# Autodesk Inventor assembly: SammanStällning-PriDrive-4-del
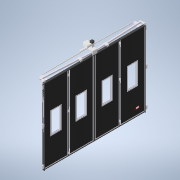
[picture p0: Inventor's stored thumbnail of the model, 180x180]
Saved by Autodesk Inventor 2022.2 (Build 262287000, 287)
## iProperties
Created: 2022-02
Part Number: SammanStällning-PriDrive-4-del
Document SubType Name: Assembly
Designer: cl
Author: cl
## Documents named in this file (23)
- G:\AutoCad\Carl Lund\3D-modeller systemlösningar\3D-modell-systemlösning-2022\SammanStällning-PriDrive-4-del.iam
- G:\AutoCad\Carl Lund\3D-modeller systemlösningar\3D-modell-systemlösning-2022\Parts\BladKomplett2022.iam
- G:\AutoCad\Carl Lund\3D-modeller systemlösningar\3D-modell-systemlösning-2022\Parts\MellanGångjärnH.ipt
- G:\AutoCad\Carl Lund\3D-modeller systemlösningar\3D-modell-systemlösning-2022\Parts\MellanGångjärnV.ipt
- G:\AutoCad\Carl Lund\3D-modeller systemlösningar\3D-modell-systemlösning-2022\Parts\Karmstyrning.ipt
- G:\AutoCad\Carl Lund\3D-modeller systemlösningar\3D-modell-systemlösning-2022\Parts\SidotätningUppe.ipt
- G:\AutoCad\Carl Lund\3D-modeller systemlösningar\3D-modell-systemlösning-2022\Parts\SidoTätning.ipt
- G:\AutoCad\Carl Lund\3D-modeller systemlösningar\3D-modell-systemlösning-2022\Parts\SläpList.ipt
- G:\AutoCad\Carl Lund\3D-modeller systemlösningar\3D-modell-systemlösning-2022\Parts\GummilistMellan.ipt
- G:\AutoCad\Carl Lund\3D-modeller systemlösningar\3D-modell-systemlösning-2022\Styrande.iam
- G:\AutoCad\Carl Lund\3D-modeller systemlösningar\3D-modell-systemlösning-2022\Parts\PriDrive\Karmgångjärn-PriDrive.ipt
- G:\AutoCad\Carl Lund\3D-modeller systemlösningar\3D-modell-systemlösning-2022\Parts\PriDrive\VinkeljärnStyrskena2.ipt
- G:\AutoCad\Carl Lund\3D-modeller systemlösningar\3D-modell-systemlösning-2022\Parts\PriDrive\VinkeljärnStyrskena.ipt
- G:\AutoCad\Carl Lund\3D-modeller systemlösningar\3D-modell-systemlösning-2022\Parts\StyrrulleH.ipt
- G:\AutoCad\Carl Lund\3D-modeller systemlösningar\3D-modell-systemlösning-2022\Parts\StyrrulleV.ipt
- G:\AutoCad\Carl Lund\3D-modeller systemlösningar\3D-modell-systemlösning-2022\Parts\MotorPlatta.ipt
- G:\AutoCad\Carl Lund\3D-modeller systemlösningar\3D-modell-systemlösning-2022\Parts\Länkarm-4Del.ipt
- G:\AutoCad\Carl Lund\3D-modeller systemlösningar\3D-modell-systemlösning-2022\Parts\Länkarm2-4Del.ipt
- G:\AutoCad\Carl Lund\3D-modeller systemlösningar\3D-modell-systemlösning-2022\Parts\MotorKåpa.ipt
- G:\AutoCad\Carl Lund\3D-modeller systemlösningar\3D-modell-systemlösning-2022\Parts\Motor.ipt
- G:\AutoCad\Carl Lund\3D-modeller systemlösningar\3D-modell-systemlösning-2022\Parts\Växellåda.ipt
- G:\AutoCad\Carl Lund\3D-modeller systemlösningar\3D-modell-systemlösning-2022\Parts\Styrskena-PD.ipt
- G:\AutoCad\Carl Lund\3D-modeller systemlösningar\3D-modell-systemlösning-2022\Parts\Logga.ipt
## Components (47 placed, 21 different names)
1. Logga:1 — Mate:196, Mate:197, Mate:198
2. BladKomplett2022:1 [sub-assembly] — Mate:1, Mate:2, Flush:1, Flush:2, Flush:3, Flush:8, Flush:28, Flush:29, Mate:28, Flush:30, Mate:42, Mate:39, Mate:43, Flush:99, Flush:100, Flush:101, Flush:102, Flush:103, Flush:104, Flush:112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
3. BladKomplett2022:2 [sub-assembly] — Flush:2, Flush:3, Flush:8, Flush:106, Mate:52, Flush:107, Flush:118, Flush:121, Mate:65, Flush:148, Flush:149, Mate:185, Flush:182, Flush:183, Flush:188, Mate:189
4. BladKomplett2022:3 [sub-assembly] — Flush:30, Flush:101, Flush:102, Mate:53, Flush:114, Flush:115, Flush:180
5. BladKomplett2022:4 [sub-assembly] — Flush:32, Flush:100, Flush:103, Mate:54, Flush:122, Flush:123, Flush:128, Mate:64, Flush:146, Flush:147, Flush:178
6. BladKomplett2022:5 [sub-assembly] — Flush:31, Flush:99, Flush:104, Flush:129, Mate:55, Flush:130, Mate:63, Flush:144, Flush:145, Mate:186, Flush:184, Flush:185, Flush:186, Flush:189
7. BladKomplett2022:6 [sub-assembly] — Mate:28, Flush:28, Flush:29, Flush:31, Flush:32, Mate:38, Flush:131, Flush:134, Flush:137, Mate:56, Flush:138, Flush:139, Mate:58, Mate:59, Mate:62, Flush:142, Flush:143, Flush:152, Mate:69, Mate:70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
8. Karmstyrning:2 — Mate:38, Mate:56, Flush:138, Flush:141
9. Karmstyrning:3 — Mate:39, Mate:43, Flush:140
10. Karmstyrning:4 — Mate:42, Mate:60, Mate:61, Flush:141
11. Karmstyrning:1 — Flush:139, Mate:58, Mate:59, Flush:140
12. MellanGångjärnV:3 — Flush:110, Flush:111, Flush:113
13. MellanGångjärnV:2 — Flush:108, Flush:109, Flush:110, Flush:111, Flush:112
14. MellanGångjärnV:1 — Flush:106, Mate:52, Flush:107, Flush:108, Flush:109
15. MellanGångjärnH:2 — Flush:116, Flush:117, Flush:118, Flush:119, Flush:120
16. MellanGångjärnH:3 — Flush:119, Flush:120, Flush:121
17. MellanGångjärnH:1 — Mate:53, Flush:114, Flush:115, Flush:116, Flush:117
18. MellanGångjärnV:6 — Flush:124, Flush:125, Flush:126, Flush:127, Flush:128
19. MellanGångjärnV:5 — Flush:126, Flush:127, Flush:129
20. MellanGångjärnV:4 — Mate:54, Flush:122, Flush:123, Flush:124, Flush:125
21. MellanGångjärnH:5 — Flush:132, Flush:133, Flush:134
22. MellanGångjärnH:6 — Flush:135, Flush:136, Flush:137
23. MellanGångjärnH:4 — Mate:55, Flush:130, Flush:131, Flush:132, Flush:133, Flush:135, Flush:136
24. GummilistMellan:2 — Mate:63, Flush:144, Flush:145
25. GummilistMellan:3 — Mate:64, Flush:146, Flush:147
26. GummilistMellan:4 — Mate:65, Flush:148, Flush:149
27. GummilistMellan:5 — Mate:66, Flush:150, Flush:151
28. SidotätningUppe:1 — Mate:67, Mate:68, Flush:152, Mate:71, Mate:74
29. SidoTätning:1 — Mate:69, Mate:70, Mate:71, Mate:76
30. SidoTätning:2 — Mate:72, Mate:73, Mate:74
31. SläpList:1 — Mate:75, Flush:153, Mate:76
32. GummilistMellan:1 — Mate:62, Flush:142, Flush:143
33. Karmgångjärn-PriDrive:1 — Mate:177, Flush:176, Mate:178, Flush:177, Flush:179, Mate:188, Tangent:3, Tangent:4
34. VinkeljärnStyrskena2:1 — Flush:179, Flush:180, Mate:181, Mate:183, Flush:187
35. VinkeljärnStyrskena2:2 — Flush:177, Flush:178, Mate:180, Flush:181, Mate:184
36. VinkeljärnStyrskena:1 — Mate:182, Flush:181, Flush:186
37. VinkeljärnStyrskena:2 — Mate:187, Flush:187, Flush:188
38. StyrrulleH:1 — Mate:185, Flush:182, Flush:183, Tangent:2
39. StyrrulleV:1 — Mate:186, Flush:184, Flush:185, Tangent:1
40. Styrskena-PD:2 — Flush:174, Mate:181, Mate:183, Tangent:2, Mate:187
41. Styrskena-PD:1 — Flush:174, Mate:179, Mate:180, Mate:182, Mate:184, Tangent:1
42. Länkarm-4Del:1 — Flush:190, Mate:190, Tangent:3, Flush:191
43. Länkarm2-4Del:1 — Mate:191, Flush:191, Tangent:4
44. MotorKåpa:1 — Mate:195, Flush:195, Flush:196
45. Motor:1 — Mate:193, Flush:194, Mate:194, Mate:195, Flush:195, Flush:196
46. Växellåda:1 — Mate:192, Flush:192, Flush:193, Flush:194, Mate:194
47. MotorPlatta:1 — Mate:188, Flush:189, Mate:189, Flush:190, Mate:190, Mate:191, Mate:192, Flush:192, Flush:193, Mate:193
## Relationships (142: Flush 85, Mate 53, Tangent 4)
- Mate:1: BladKomplett2022:1
- Mate:2: BladKomplett2022:1
- Flush:1: BladKomplett2022:1
- Flush:2: BladKomplett2022:1 ↔ BladKomplett2022:2
- Flush:3: BladKomplett2022:1 ↔ BladKomplett2022:2
- Flush:8: BladKomplett2022:1 ↔ BladKomplett2022:2
- Mate:28: BladKomplett2022:1 ↔ BladKomplett2022:6
- Flush:28: BladKomplett2022:1 ↔ BladKomplett2022:6
- Flush:29: BladKomplett2022:1 ↔ BladKomplett2022:6
- Flush:30: BladKomplett2022:1 ↔ BladKomplett2022:3
- Flush:31: BladKomplett2022:5 ↔ BladKomplett2022:6
- Flush:32: BladKomplett2022:4 ↔ BladKomplett2022:6
- Mate:38: BladKomplett2022:6 ↔ Karmstyrning:2
- Mate:39: BladKomplett2022:1 ↔ Karmstyrning:3
- Mate:42: BladKomplett2022:1 ↔ Karmstyrning:4
- Mate:43: BladKomplett2022:1 ↔ Karmstyrning:3
- Flush:99: BladKomplett2022:1 ↔ BladKomplett2022:5
- Flush:100: BladKomplett2022:1 ↔ BladKomplett2022:4
- Flush:101: BladKomplett2022:1 ↔ BladKomplett2022:3
- Flush:102: BladKomplett2022:1 ↔ BladKomplett2022:3
- Flush:103: BladKomplett2022:1 ↔ BladKomplett2022:4
- Flush:104: BladKomplett2022:1 ↔ BladKomplett2022:5
- Flush:106: BladKomplett2022:2 ↔ MellanGångjärnV:1
- Mate:52: BladKomplett2022:2 ↔ MellanGångjärnV:1
- Flush:107: BladKomplett2022:2 ↔ MellanGångjärnV:1
- Flush:108: MellanGångjärnV:2 ↔ MellanGångjärnV:1
- Flush:109: MellanGångjärnV:2 ↔ MellanGångjärnV:1
- Flush:110: MellanGångjärnV:3 ↔ MellanGångjärnV:2
- Flush:111: MellanGångjärnV:3 ↔ MellanGångjärnV:2
- Flush:112: BladKomplett2022:1 ↔ MellanGångjärnV:2
- Flush:113: BladKomplett2022:1 ↔ MellanGångjärnV:3
- Mate:53: BladKomplett2022:3 ↔ MellanGångjärnH:1
- Flush:114: BladKomplett2022:3 ↔ MellanGångjärnH:1
- Flush:115: BladKomplett2022:3 ↔ MellanGångjärnH:1
- Flush:116: MellanGångjärnH:2 ↔ MellanGångjärnH:1
- Flush:117: MellanGångjärnH:2 ↔ MellanGångjärnH:1
- Flush:118: BladKomplett2022:2 ↔ MellanGångjärnH:2
- Flush:119: MellanGångjärnH:2 ↔ MellanGångjärnH:3
- Flush:120: MellanGångjärnH:2 ↔ MellanGångjärnH:3
- Flush:121: BladKomplett2022:2 ↔ MellanGångjärnH:3
- Mate:54: BladKomplett2022:4 ↔ MellanGångjärnV:4
- Flush:122: BladKomplett2022:4 ↔ MellanGångjärnV:4
- Flush:123: BladKomplett2022:4 ↔ MellanGångjärnV:4
- Flush:124: MellanGångjärnV:6 ↔ MellanGångjärnV:4
- Flush:125: MellanGångjärnV:6 ↔ MellanGångjärnV:4
- Flush:126: MellanGångjärnV:6 ↔ MellanGångjärnV:5
- Flush:127: MellanGångjärnV:6 ↔ MellanGångjärnV:5
- Flush:128: BladKomplett2022:4 ↔ MellanGångjärnV:6
- Flush:129: BladKomplett2022:5 ↔ MellanGångjärnV:5
- Mate:55: BladKomplett2022:5 ↔ MellanGångjärnH:4
- Flush:130: BladKomplett2022:5 ↔ MellanGångjärnH:4
- Flush:131: BladKomplett2022:6 ↔ MellanGångjärnH:4
- Flush:132: MellanGångjärnH:5 ↔ MellanGångjärnH:4
- Flush:133: MellanGångjärnH:5 ↔ MellanGångjärnH:4
- Flush:134: BladKomplett2022:6 ↔ MellanGångjärnH:5
- Flush:135: MellanGångjärnH:6 ↔ MellanGångjärnH:4
- Flush:136: MellanGångjärnH:6 ↔ MellanGångjärnH:4
- Flush:137: BladKomplett2022:6 ↔ MellanGångjärnH:6
- Mate:56: BladKomplett2022:6 ↔ Karmstyrning:2
- Flush:138: BladKomplett2022:6 ↔ Karmstyrning:2
- Flush:139: BladKomplett2022:6 ↔ Karmstyrning:1
- Mate:58: BladKomplett2022:6 ↔ Karmstyrning:1
- Mate:59: BladKomplett2022:6 ↔ Karmstyrning:1
- Flush:140: Karmstyrning:3 ↔ Karmstyrning:1
- Mate:60: BladKomplett2022:1 ↔ Karmstyrning:4
- Mate:61: BladKomplett2022:1 ↔ Karmstyrning:4
- Flush:141: Karmstyrning:2 ↔ Karmstyrning:4
- Mate:62: BladKomplett2022:6 ↔ GummilistMellan:1
- Flush:142: BladKomplett2022:6 ↔ GummilistMellan:1
- Flush:143: BladKomplett2022:6 ↔ GummilistMellan:1
- Mate:63: BladKomplett2022:5 ↔ GummilistMellan:2
- Flush:144: BladKomplett2022:5 ↔ GummilistMellan:2
- Flush:145: BladKomplett2022:5 ↔ GummilistMellan:2
- Mate:64: BladKomplett2022:4 ↔ GummilistMellan:3
- Flush:146: BladKomplett2022:4 ↔ GummilistMellan:3
- Flush:147: BladKomplett2022:4 ↔ GummilistMellan:3
- Mate:65: BladKomplett2022:2 ↔ GummilistMellan:4
- Flush:148: BladKomplett2022:2 ↔ GummilistMellan:4
- Flush:149: BladKomplett2022:2 ↔ GummilistMellan:4
- Mate:66: BladKomplett2022:1 ↔ GummilistMellan:5
- Flush:150: BladKomplett2022:1 ↔ GummilistMellan:5
- Flush:151: BladKomplett2022:1 ↔ GummilistMellan:5
- Mate:67: BladKomplett2022:1 ↔ SidotätningUppe:1
- Mate:68: BladKomplett2022:1 ↔ SidotätningUppe:1
- Flush:152: BladKomplett2022:6 ↔ SidotätningUppe:1
- Mate:69: BladKomplett2022:6 ↔ SidoTätning:1
- Mate:70: BladKomplett2022:6 ↔ SidoTätning:1
- Mate:71: SidotätningUppe:1 ↔ SidoTätning:1
- Mate:72: BladKomplett2022:1 ↔ SidoTätning:2
- Mate:73: BladKomplett2022:1 ↔ SidoTätning:2
- Mate:74: SidotätningUppe:1 ↔ SidoTätning:2
- Mate:75: BladKomplett2022:1 ↔ SläpList:1
- Flush:153: BladKomplett2022:1 ↔ SläpList:1
- Mate:76: SidoTätning:1 ↔ SläpList:1
- Flush:174: Styrskena-PD:2 ↔ Styrskena-PD:1
- Mate:177: BladKomplett2022:1 ↔ Karmgångjärn-PriDrive:1
- Flush:176: BladKomplett2022:1 ↔ Karmgångjärn-PriDrive:1
- Mate:178: BladKomplett2022:1 ↔ Karmgångjärn-PriDrive:1
- Flush:177: Karmgångjärn-PriDrive:1 ↔ VinkeljärnStyrskena2:2
- Flush:178: BladKomplett2022:4 ↔ VinkeljärnStyrskena2:2
- Mate:179: BladKomplett2022:6 ↔ Styrskena-PD:1
- Mate:180: VinkeljärnStyrskena2:2 ↔ Styrskena-PD:1
- Flush:179: Karmgångjärn-PriDrive:1 ↔ VinkeljärnStyrskena2:1
- Flush:180: BladKomplett2022:3 ↔ VinkeljärnStyrskena2:1
- Mate:181: VinkeljärnStyrskena2:1 ↔ Styrskena-PD:2
- Mate:182: VinkeljärnStyrskena:1 ↔ Styrskena-PD:1
- Flush:181: VinkeljärnStyrskena2:2 ↔ VinkeljärnStyrskena:1
- Mate:183: VinkeljärnStyrskena2:1 ↔ Styrskena-PD:2
- Mate:184: VinkeljärnStyrskena2:2 ↔ Styrskena-PD:1
- Mate:185: BladKomplett2022:2 ↔ StyrrulleH:1
- Flush:182: BladKomplett2022:2 ↔ StyrrulleH:1
- Flush:183: BladKomplett2022:2 ↔ StyrrulleH:1
- Mate:186: BladKomplett2022:5 ↔ StyrrulleV:1
- Flush:184: BladKomplett2022:5 ↔ StyrrulleV:1
- Flush:185: BladKomplett2022:5 ↔ StyrrulleV:1
- Tangent:1: StyrrulleV:1 ↔ Styrskena-PD:1
- Tangent:2: StyrrulleH:1 ↔ Styrskena-PD:2
- Flush:186: BladKomplett2022:5 ↔ VinkeljärnStyrskena:1
- Mate:187: VinkeljärnStyrskena:2 ↔ Styrskena-PD:2
- Flush:187: VinkeljärnStyrskena2:1 ↔ VinkeljärnStyrskena:2
- Flush:188: BladKomplett2022:2 ↔ VinkeljärnStyrskena:2
- Mate:188: Karmgångjärn-PriDrive:1 ↔ MotorPlatta:1
- Flush:189: BladKomplett2022:5 ↔ MotorPlatta:1
- Mate:189: BladKomplett2022:2 ↔ MotorPlatta:1
- Flush:190: Länkarm-4Del:1 ↔ MotorPlatta:1
- Mate:190: Länkarm-4Del:1 ↔ MotorPlatta:1
- Tangent:3: Karmgångjärn-PriDrive:1 ↔ Länkarm-4Del:1
- Mate:191: Länkarm2-4Del:1 ↔ MotorPlatta:1
- Flush:191: Länkarm-4Del:1 ↔ Länkarm2-4Del:1
- Tangent:4: Karmgångjärn-PriDrive:1 ↔ Länkarm2-4Del:1
- Mate:192: Växellåda:1 ↔ MotorPlatta:1
- Flush:192: Växellåda:1 ↔ MotorPlatta:1
- Flush:193: Växellåda:1 ↔ MotorPlatta:1
- Mate:193: Motor:1 ↔ MotorPlatta:1
- Flush:194: Motor:1 ↔ Växellåda:1
- Mate:194: Motor:1 ↔ Växellåda:1
- Mate:195: MotorKåpa:1 ↔ Motor:1
- Flush:195: MotorKåpa:1 ↔ Motor:1
- Flush:196: MotorKåpa:1 ↔ Motor:1
- Mate:196: Logga:1 ↔ BladKomplett2022:6
- Mate:197: Logga:1 ↔ BladKomplett2022:6
- Mate:198: Logga:1 ↔ BladKomplett2022:6
## Named parameters: Blad2 = 1012.5 mm, Blad3 = 0, Blad4 = 0, Blad5 = 1012.5 mm, MGJ12Djup = 0, MGJ12Bredd = 0, MGJ56Djup = 0, MGJ56Bredd = 0, MGJ23Djup = 48 mm, MGJ45Djup = 48 mm, GarageRegel5 = 0, GarageRegel6 = 0, BladBredd = 987.5 mm, Fönsterhöjd = 862 mm, Blad2_1 = 1012.5 mm, Blad3_1 = 0, Blad4_1 = 0, Blad5_1 = 1012.5 mm, Blad6 = 2025 mm, MGJ12Djup_1 = 0, MGJ12Bredd_1 = 0, MGJ2Djup = 0, MGJ2Bredd = 5012.5 mm, MGJ56Djup_1 = 0, MGJ56Bredd_1 = 0, MGJ23Djup_1 = 48 mm, MGJ45Djup_1 = 48 mm, GarageRegel5_1 = 0, GarageRegel6_1 = 0, Styrrulle2Djup = 0, FönsterhöjdStyrning = 862 mm, FönsterKarm = 54 mm, AndraGlasraden = 0, BrösthöjdStyrning2 = 0.0001 mm, InfälldGångDörr = 0, Infälldstyr = 1030.33333 mm, EnDelGångDörr = 0, VinkelJärnStyrSkena = 1456.25 mm
